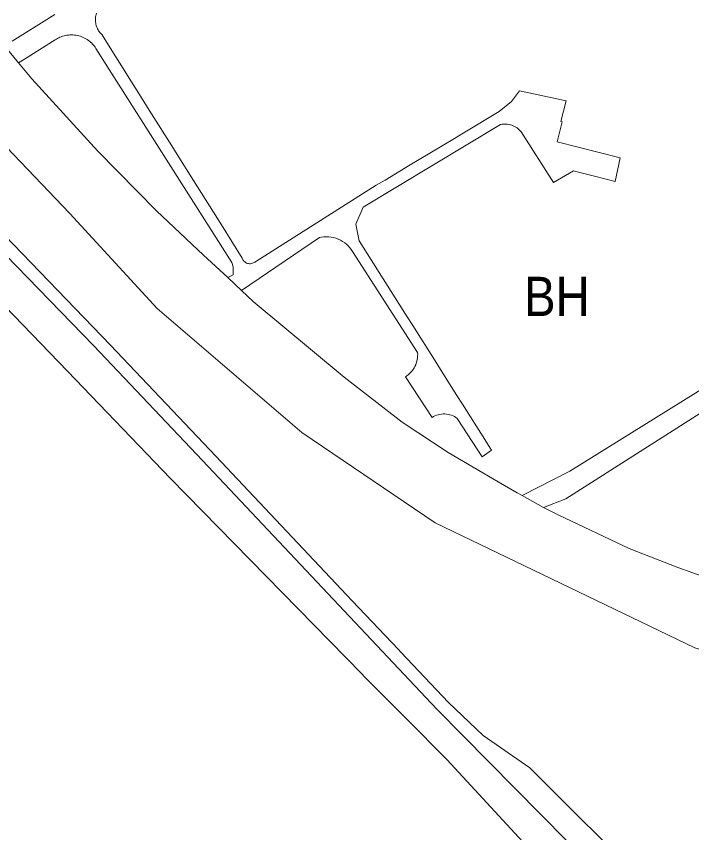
# Model space of a CAD drawing. Extents: x -650451 to -642268, y -1075216 to -1066610.
# Drawn here: x -647083.9 to -646877.8, y -1072156.5 to -1071907.4 of the extents above; entities that cross this region are included whole.
import ezdxf

# ---------------------------------------------------------------- set-up
doc = ezdxf.new("R2010")
doc.units = 0
doc.header["$LTSCALE"] = 4.8
for name, color, linetype, lineweight in [('1', 7, 'Continuous', 13), ('15', 7, 'Continuous', 13), ('24', 7, 'Continuous', 13), ('25', 7, 'Continuous', 13)]:
    doc.layers.add(name, color=color, linetype=linetype, lineweight=lineweight)
doc.layers.add('62', color=7, linetype='Continuous')

msp = doc.modelspace()

# ---------------------------------------------------------------- linework, layer by layer
at = {"layer": '1'}
msp.add_line((-647059.764, -1071908.683), (-647059.773, -1071908.305), dxfattribs=at)
for points in [[(-647072.19, -1071906.77), (-647085.18, -1071914.96)], [(-647059.773, -1071908.305), (-647059.759, -1071907.927), (-647059.722, -1071907.55), (-647059.663, -1071907.177), (-647059.582, -1071906.809), (-647059.48, -1071906.449)], [(-646955.166, -1072028.985), (-646954.665, -1072028.862), (-646954.15, -1072028.778), (-646953.627, -1072028.735), (-646953.101, -1072028.733), (-646952.576, -1072028.774), (-646952.057, -1072028.855), (-646951.55, -1072028.976), (-646951.058, -1072029.135), (-646950.587, -1072029.33), (-646950.138, -1072029.556), (-646949.715, -1072029.811), (-646949.32, -1072030.09), (-646941.69, -1072041.83), (-646938.83, -1072039.79), (-646939.24, -1072039.15), (-646940.88, -1072036.53), (-646947.75, -1072025.72), (-646949.41, -1072023.1), (-646954.42, -1072015.17), (-646956.08, -1072012.55), (-646962.92, -1072001.71), (-646964.58, -1071999.1), (-646979.29, -1071975.87), (-646980.24, -1071970.82), (-646978.07, -1071965.64), (-646936.09, -1071940.35), (-646935.674, -1071940.285), (-646935.247, -1071940.246), (-646934.814, -1071940.235), (-646934.376, -1071940.252), (-646933.936, -1071940.299), (-646933.497, -1071940.377), (-646933.062, -1071940.484), (-646932.635, -1071940.62), (-646932.218, -1071940.785), (-646931.814, -1071940.978), (-646931.425, -1071941.196), (-646931.055, -1071941.438), (-646930.705, -1071941.702), (-646930.376, -1071941.986), (-646930.071, -1071942.286), (-646929.79, -1071942.6), (-646919.94, -1071958.07), (-646913.8, -1071954.56), (-646913.12, -1071954.73), (-646907.39, -1071956.2), (-646901.12, -1071957.8), (-646899.57, -1071950.59), (-646918.8, -1071945.71), (-646917.27, -1071939.61), (-646917.68, -1071939.52), (-646916.11, -1071933.14), (-646930.36, -1071930.12), (-646932.73, -1071933.38), (-646936.54, -1071936.4), (-646947.55, -1071943.04), (-646950.16, -1071944.61), (-646960.99, -1071951.09), (-646963.66, -1071952.69), (-646971.36, -1071957.34), (-646974.03, -1071958.93), (-647011.12, -1071982.36), (-647011.333, -1071982.509), (-647011.571, -1071982.64), (-647011.834, -1071982.748), (-647012.119, -1071982.828), (-647012.421, -1071982.873), (-647012.733, -1071982.881), (-647013.05, -1071982.849), (-647013.362, -1071982.776), (-647013.661, -1071982.663), (-647013.942, -1071982.513), (-647014.197, -1071982.332), (-647014.421, -1071982.126), (-647014.613, -1071981.901), (-647014.772, -1071981.664), (-647014.896, -1071981.422), (-647014.99, -1071981.18), (-647021.33, -1071971.05), (-647029.84, -1071957.53), (-647034.82, -1071949.57), (-647036.46, -1071946.94), (-647043.33, -1071936), (-647044.98, -1071933.37), (-647056.79, -1071914.57), (-647057.73, -1071913), (-647057.954, -1071912.784), (-647058.172, -1071912.551), (-647058.382, -1071912.303), (-647058.583, -1071912.039), (-647058.773, -1071911.759), (-647058.952, -1071911.464), (-647059.116, -1071911.155), (-647059.265, -1071910.832), (-647059.397, -1071910.496), (-647059.511, -1071910.15), (-647059.606, -1071909.794), (-647059.68, -1071909.429), (-647059.733, -1071909.058), (-647059.764, -1071908.683)], [(-647083.23, -1071921.57), (-647081.42, -1071920.42), (-647072.02, -1071914.52), (-647071.682, -1071914.305), (-647071.329, -1071914.103), (-647070.96, -1071913.913), (-647070.577, -1071913.739), (-647070.179, -1071913.581), (-647069.769, -1071913.44), (-647069.347, -1071913.318), (-647068.914, -1071913.216), (-647068.472, -1071913.135), (-647068.022, -1071913.077), (-647067.566, -1071913.041), (-647067.106, -1071913.029), (-647066.643, -1071913.041), (-647066.179, -1071913.077), (-647065.717, -1071913.137), (-647065.258, -1071913.223), (-647064.804, -1071913.332), (-647064.357, -1071913.464), (-647063.919, -1071913.62), (-647063.491, -1071913.798), (-647063.076, -1071913.996), (-647062.674, -1071914.214), (-647062.287, -1071914.451), (-647061.916, -1071914.705), (-647061.562, -1071914.974), (-647061.226, -1071915.257), (-647060.909, -1071915.553), (-647060.61, -1071915.859), (-647060.331, -1071916.175), (-647060.071, -1071916.497), (-647059.831, -1071916.826), (-647059.61, -1071917.16), (-647018.16, -1071982.46), (-647017.68, -1071983.79), (-647017.74, -1071986.23), (-647019.3, -1071987.12)], [(-647019.3, -1071987.12), (-647026.77, -1071980.29), (-647041.08, -1071966.71), (-647059.01, -1071948.52), (-647079.15, -1071926.49), (-647083.23, -1071921.57)], [(-646966.13, -1072031.23), (-646983.88, -1072017.52), (-647011.61, -1071994.42), (-647015.13, -1071991.01), (-646991.41, -1071974.91)], [(-646991.41, -1071974.91), (-646990.73, -1071974.771), (-646990.026, -1071974.681), (-646989.303, -1071974.646)], [(-646989.303, -1071974.646), (-646988.568, -1071974.668), (-646987.828, -1071974.75), (-646987.089, -1071974.894)], [(-646987.089, -1071974.894), (-646986.36, -1071975.098), (-646985.647, -1071975.362), (-646984.958, -1071975.684)], [(-646984.958, -1071975.684), (-646984.301, -1071976.061), (-646983.68, -1071976.486), (-646983.102, -1071976.956), (-646982.571, -1071977.464), (-646982.089, -1071978.003)], [(-646982.089, -1071978.003), (-646981.658, -1071978.568), (-646981.28, -1071979.15), (-646961.43, -1072010.01), (-646961.403, -1072010.528), (-646961.411, -1072011.056), (-646961.456, -1072011.589), (-646961.537, -1072012.125), (-646961.656, -1072012.658), (-646961.813, -1072013.186), (-646962.008, -1072013.705), (-646962.239, -1072014.209), (-646962.505, -1072014.696), (-646962.804, -1072015.162), (-646963.133, -1072015.604), (-646963.489, -1072016.019)], [(-646838.9, -1072005.5), (-646835.37, -1072002.93), (-646833.87, -1071996.79), (-646834.3, -1071996.69), (-646832.72, -1071990.28), (-646839.28, -1071988.56), (-646841.53, -1071997.7), (-646842.99, -1072001.02), (-646845.34, -1072002.9), (-646850.15, -1072005.88), (-646914.94, -1072046.17), (-646929.53, -1072053.65), (-646931, -1072052.81)], [(-646963.489, -1072016.019), (-646963.87, -1072016.405), (-646964.271, -1072016.759), (-646964.689, -1072017.081), (-646965.12, -1072017.37), (-646956.97, -1072029.81)], [(-646922.95, -1072057.25), (-646916.18, -1072054.65), (-646868.52, -1072024.34), (-646866.94, -1072023.74), (-646864.5, -1072023.38)], [(-646956.97, -1072029.81), (-646956.556, -1072029.56), (-646956.115, -1072029.337), (-646955.651, -1072029.144), (-646955.166, -1072028.985)], [(-646931, -1072052.81), (-646936.81, -1072049.5), (-646952.07, -1072040.55), (-646966.13, -1072031.23)], [(-646843.68, -1072088.06), (-646846.81, -1072087.28), (-646863.68, -1072082.09), (-646881.98, -1072075.61), (-646896.84, -1072069.83), (-646918.32, -1072059.65), (-646922.95, -1072057.25)]]:
    msp.add_lwpolyline(points, dxfattribs=at)
at = {"layer": '15'}
msp.add_line((-646955.166, -1072028.985), (-646955.651, -1072029.144), dxfattribs=at)
for points in [[(-646900.046, -1072175.154), (-646955.57, -1072118.88), (-647027.11, -1072042.92), (-647060.23, -1072007.95), (-647104.1, -1071962.84), (-647177.46, -1071886.9), (-647221.71, -1071838.15), (-647262.68, -1071796.7), (-647265.83, -1071793.64)], [(-647085.18, -1071914.96), (-647072.19, -1071906.77)], [(-647059.582, -1071906.809), (-647059.663, -1071907.177), (-647059.722, -1071907.55), (-647059.759, -1071907.927), (-647059.773, -1071908.305), (-647059.764, -1071908.683)], [(-647059.764, -1071908.683), (-647059.733, -1071909.058), (-647059.68, -1071909.429), (-647059.606, -1071909.794), (-647059.511, -1071910.15), (-647059.397, -1071910.496), (-647059.265, -1071910.832), (-647059.116, -1071911.155), (-647058.952, -1071911.464), (-647058.773, -1071911.759), (-647058.583, -1071912.039), (-647058.382, -1071912.303), (-647058.172, -1071912.551), (-647057.954, -1071912.784), (-647057.73, -1071913), (-647056.79, -1071914.57), (-647044.98, -1071933.37), (-647043.33, -1071936), (-647036.46, -1071946.94), (-647034.82, -1071949.57), (-647029.84, -1071957.53), (-647021.33, -1071971.05), (-647014.99, -1071981.18), (-647014.896, -1071981.422), (-647014.772, -1071981.664), (-647014.613, -1071981.901), (-647014.421, -1071982.126), (-647014.197, -1071982.332), (-647013.942, -1071982.513), (-647013.661, -1071982.663), (-647013.362, -1071982.776), (-647013.05, -1071982.849), (-647012.733, -1071982.881), (-647012.421, -1071982.873), (-647012.119, -1071982.828), (-647011.834, -1071982.748), (-647011.571, -1071982.64), (-647011.333, -1071982.509), (-647011.12, -1071982.36), (-646974.03, -1071958.93), (-646971.36, -1071957.34), (-646963.66, -1071952.69), (-646960.99, -1071951.09), (-646950.16, -1071944.61), (-646947.55, -1071943.04), (-646936.54, -1071936.4), (-646932.73, -1071933.38), (-646930.36, -1071930.12), (-646916.11, -1071933.14), (-646917.68, -1071939.52), (-646917.27, -1071939.61), (-646918.8, -1071945.71), (-646899.57, -1071950.59), (-646901.12, -1071957.8), (-646907.39, -1071956.2), (-646913.12, -1071954.73), (-646913.8, -1071954.56), (-646919.94, -1071958.07), (-646929.79, -1071942.6), (-646930.071, -1071942.286), (-646930.376, -1071941.986), (-646930.705, -1071941.702), (-646931.055, -1071941.438), (-646931.425, -1071941.196), (-646931.814, -1071940.978), (-646932.218, -1071940.785), (-646932.635, -1071940.62), (-646933.062, -1071940.484), (-646933.497, -1071940.377), (-646933.936, -1071940.299), (-646934.376, -1071940.252), (-646934.814, -1071940.235), (-646935.247, -1071940.246), (-646935.674, -1071940.285), (-646936.09, -1071940.35), (-646978.07, -1071965.64), (-646980.24, -1071970.82), (-646979.29, -1071975.87), (-646964.58, -1071999.1), (-646962.92, -1072001.71), (-646956.08, -1072012.55), (-646954.42, -1072015.17), (-646949.41, -1072023.1), (-646947.75, -1072025.72), (-646940.88, -1072036.53), (-646939.24, -1072039.15), (-646938.83, -1072039.79), (-646941.69, -1072041.83), (-646949.32, -1072030.09), (-646949.715, -1072029.811), (-646950.138, -1072029.556), (-646950.587, -1072029.33), (-646951.058, -1072029.135), (-646951.55, -1072028.976), (-646952.057, -1072028.855), (-646952.576, -1072028.774), (-646953.101, -1072028.733), (-646953.627, -1072028.735), (-646954.15, -1072028.778), (-646954.665, -1072028.862), (-646955.166, -1072028.985)], [(-647019.3, -1071987.12), (-647017.74, -1071986.23), (-647017.68, -1071983.79), (-647018.16, -1071982.46), (-647059.61, -1071917.16), (-647059.831, -1071916.826), (-647060.071, -1071916.497), (-647060.331, -1071916.175), (-647060.61, -1071915.859), (-647060.909, -1071915.553), (-647061.226, -1071915.257), (-647061.562, -1071914.974), (-647061.916, -1071914.705), (-647062.287, -1071914.451), (-647062.674, -1071914.214), (-647063.076, -1071913.996), (-647063.491, -1071913.798), (-647063.919, -1071913.62), (-647064.357, -1071913.464), (-647064.804, -1071913.332), (-647065.258, -1071913.223), (-647065.717, -1071913.137), (-647066.179, -1071913.077), (-647066.643, -1071913.041), (-647067.106, -1071913.029), (-647067.566, -1071913.041), (-647068.022, -1071913.077), (-647068.472, -1071913.135), (-647068.914, -1071913.216), (-647069.347, -1071913.318), (-647069.769, -1071913.44), (-647070.179, -1071913.581), (-647070.577, -1071913.739), (-647070.96, -1071913.913), (-647071.329, -1071914.103), (-647071.682, -1071914.305), (-647072.02, -1071914.52), (-647081.42, -1071920.42), (-647083.23, -1071921.57), (-647088.04, -1071915.77)], [(-647131.146, -1071929.146), (-647101.07, -1071960.24), (-647055.16, -1072007.74), (-647023.04, -1072041.63), (-646981.35, -1072085.77), (-646967.25, -1072100.6), (-646966.54, -1072101.4), (-646951.95, -1072116.84), (-646941.45, -1072126.84), (-646927.14, -1072136.74), (-646891.05, -1072172.79), (-646890.044, -1072174.056), (-646900.046, -1072175.154)], [(-646989.303, -1071974.646), (-646990.026, -1071974.681), (-646990.73, -1071974.771), (-646991.41, -1071974.91), (-647015.13, -1071991.01), (-647019.3, -1071987.12)], [(-646987.089, -1071974.894), (-646987.828, -1071974.75), (-646988.568, -1071974.668), (-646989.303, -1071974.646)], [(-646984.958, -1071975.684), (-646985.647, -1071975.362), (-646986.36, -1071975.098), (-646987.089, -1071974.894)], [(-646983.102, -1071976.956), (-646983.68, -1071976.486), (-646984.301, -1071976.061), (-646984.958, -1071975.684)], [(-646961.813, -1072013.186), (-646961.656, -1072012.658), (-646961.537, -1072012.125), (-646961.456, -1072011.589), (-646961.411, -1072011.056), (-646961.403, -1072010.528), (-646961.43, -1072010.01), (-646981.28, -1071979.15), (-646981.658, -1071978.568), (-646982.089, -1071978.003), (-646982.571, -1071977.464), (-646983.102, -1071976.956)], [(-646929.53, -1072053.65), (-646914.94, -1072046.17), (-646850.15, -1072005.88), (-646845.34, -1072002.9), (-646842.99, -1072001.02), (-646841.53, -1071997.7), (-646839.28, -1071988.56), (-646832.72, -1071990.28), (-646834.3, -1071996.69), (-646833.87, -1071996.79), (-646835.37, -1072002.93), (-646838.9, -1072005.5)], [(-646964.689, -1072017.081), (-646964.271, -1072016.759), (-646963.87, -1072016.405), (-646963.489, -1072016.019), (-646963.133, -1072015.604), (-646962.804, -1072015.162), (-646962.505, -1072014.696), (-646962.239, -1072014.209), (-646962.008, -1072013.705), (-646961.813, -1072013.186)], [(-646955.651, -1072029.144), (-646956.115, -1072029.337), (-646956.556, -1072029.56), (-646956.97, -1072029.81), (-646965.12, -1072017.37), (-646964.689, -1072017.081)], [(-646868.52, -1072024.34), (-646916.18, -1072054.65), (-646922.95, -1072057.25), (-646929.53, -1072053.65)]]:
    msp.add_lwpolyline(points, dxfattribs=at)
at = {"layer": '24'}
for points in [[(-647162.98, -1071801.68), (-647136.28, -1071846.08), (-647121.15, -1071869.68), (-647123, -1071870.89), (-647109.58, -1071889.27), (-647094.25, -1071908.29), (-647088.04, -1071915.77), (-647083.23, -1071921.57)], [(-646743.596, -1072115.986), (-646763.93, -1072117.61), (-646771.31, -1072117.49), (-646806.87, -1072116.94), (-646832.01, -1072113.66), (-646868.61, -1072102.6), (-646876.83, -1072100.12), (-646956.04, -1072061.95), (-646996.8, -1072034.35), (-647040.89, -1071996.58), (-647067.53, -1071967.54), (-647095.51, -1071938.39), (-647114.479, -1071912.479)], [(-647083.23, -1071921.57), (-647079.15, -1071926.49), (-647059.01, -1071948.52), (-647041.08, -1071966.71), (-647026.77, -1071980.29), (-647019.3, -1071987.12), (-647015.13, -1071991.01), (-647011.61, -1071994.42)], [(-647011.61, -1071994.42), (-646983.88, -1072017.52), (-646966.13, -1072031.23), (-646952.07, -1072040.55)], [(-646952.07, -1072040.55), (-646936.81, -1072049.5), (-646931, -1072052.81), (-646929.53, -1072053.65), (-646922.95, -1072057.25), (-646918.32, -1072059.65)], [(-646918.32, -1072059.65), (-646896.84, -1072069.83), (-646881.98, -1072075.61), (-646863.68, -1072082.09), (-646846.81, -1072087.28), (-646843.68, -1072088.06)]]:
    msp.add_lwpolyline(points, dxfattribs=at)
at = {"layer": '25'}
for points in [[(-647265.83, -1071793.64), (-647262.68, -1071796.7), (-647221.71, -1071838.15), (-647177.46, -1071886.9), (-647104.1, -1071962.84), (-647060.23, -1072007.95), (-647027.11, -1072042.92), (-646955.57, -1072118.88), (-646900.046, -1072175.154), (-646913.373, -1072176.618)], [(-646913.373, -1072176.618), (-646942.78, -1072144.74), (-646952.48, -1072134.22), (-646964.8, -1072121.83), (-646977.59, -1072108.96), (-646978.45, -1072108.09), (-647036.8, -1072048.41), (-647068.31, -1072015.68), (-647114.59, -1071967.77), (-647145.38, -1071935), (-647173.14, -1071905.45), (-647174.57, -1071904.06), (-647176.32, -1071902.3), (-647209.94, -1071868.59)]]:
    msp.add_lwpolyline(points, dxfattribs=at)

# ---------------------------------------------------------------- texts
at = {"layer": '62', "width": 0.9}
msp.add_text('BH', height=12, dxfattribs=at).set_placement((-646928.941, -1071998.869))

doc.saveas('drawing.dxf')
